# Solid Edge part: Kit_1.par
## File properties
Author: bmolnar
Last saved by: bmolnar
Revision: 78
Sűrűség: 0,000 kg/m^3
Pontosság: 0,990
Username: bmolnar
Dokumentum tartalom típus: 0
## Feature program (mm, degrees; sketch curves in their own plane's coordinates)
base feature "unnamed BaseFeature 1"
sketch for "unnamed Hole 1" plane through (-36, -36, 14) normal (0, 0, 1) x-axis (0, 1, 0)
  line (0, 0) -> (0, 0)
  hole centre (0, 0) bore radius 4.188
hole "unnamed Hole 1" through
sketch for "unnamed Hole 2" plane through (-36, -36, 14) normal (0, 0, 1) x-axis (0, 1, 0)
  hole centre (72, 0) bore radius 4.188
hole "unnamed Hole 2" through
sketch for "unnamed Hole 3" plane through (-36, -36, 14) normal (0, 0, 1) x-axis (0, 1, 0)
  hole centre (72, -72) bore radius 4.188
hole "unnamed Hole 3" through
sketch for "unnamed Hole 4" plane through (-36, -36, 14) normal (0, 0, 1) x-axis (0, 1, 0)
  hole centre (0, -72) bore radius 4.188
hole "unnamed Hole 4" through
pattern "unnamed Pattern 1" of "unnamed Hole 1", "unnamed Hole 2", "unnamed Hole 3", "unnamed Hole 4"
thread "unnamed Thread 1"
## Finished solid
Body 1: solid body, 294 faces, 719 edges, 443 vertices.
  Faces by surface: plane 138, cylinder 72, swept 60, cone 15, torus 8, spline 1
  Edges by curve: line 421, circle 137, spline 120, ellipse 32, curve on surface 8, intersection 1
Bounding box of the edges (mm; curved faces can reach further): 95.500 x 95.500 x 15.000, from (-47.75, -47.75, 2) to (47.75, 47.75, 17).
Cylindrical faces by radius (mm): R0.2 x48, R0.2017 x2, R0.2018 x2, R2.5 x1, R4.188 x4, R4.283 x1, R4.9 x4, R5.15 x4, R6 x1, R6.75 x4, R21.1047 x1
Conical faces (half-angle, radius in mm at the cone's reference point): 0.5 deg R10 x4, 0.5 deg R13.5 x2, 45 deg R4.185 x4, 45 deg R4.985 x4, 45 deg R6.25 x1
Toroidal faces (ring radius, tube radius in mm): R4.7 r0.2 x8
Planar faces by outward normal: +x 14, +y 13, +z 18, -x 17, -y 14, -z 1, oblique 61
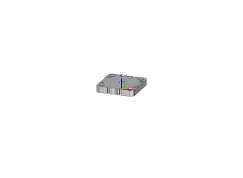
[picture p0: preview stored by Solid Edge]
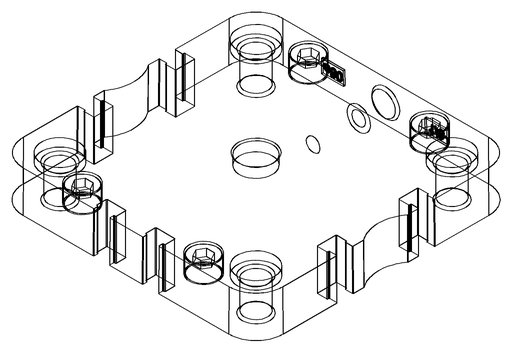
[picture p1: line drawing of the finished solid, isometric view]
